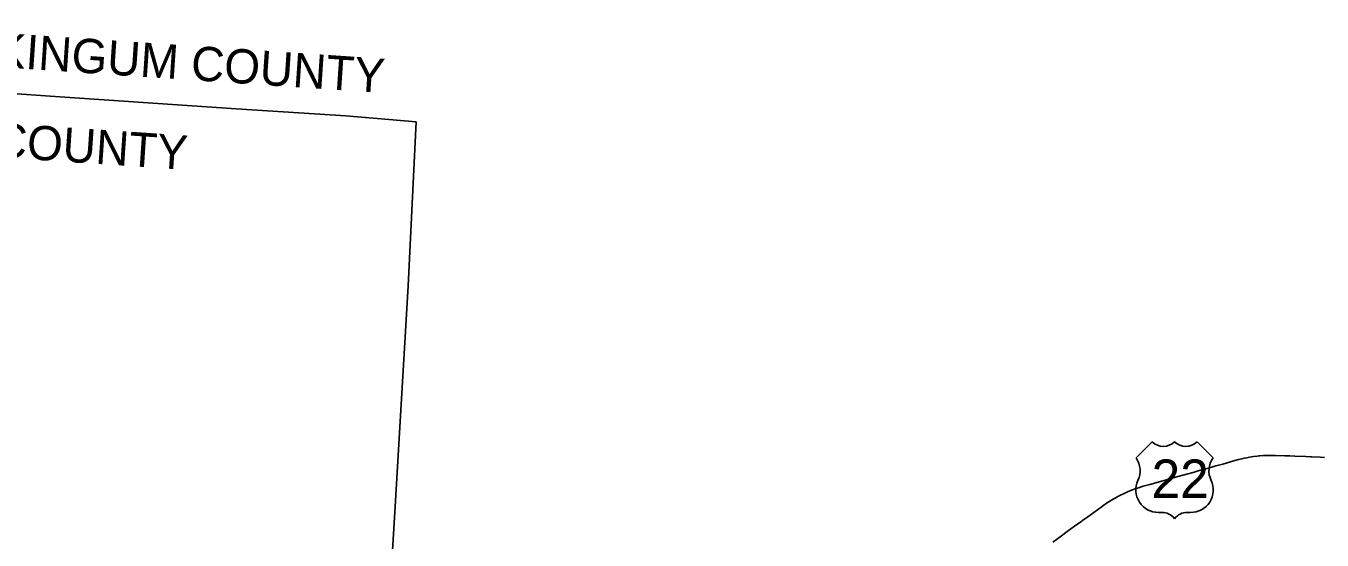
# Model space of a CAD drawing. Extents: x 2015843 to 2287843, y 623733 to 799733.
# Drawn here: x 2066735 to 2104493, y 678304 to 693294 of the extents above; entities that cross this region are included whole.
import ezdxf

# ---------------------------------------------------------------- set-up
doc = ezdxf.new("R2010")
doc.units = 0
for name, color, linetype in [('GM_X_County', 7, 'Continuous'), ('GM_X_County_Text', 7, 'Continuous'), ('GM_X_US_Location', 7, 'Continuous'), ('GM_X_US_Route', 7, 'Continuous'), ('GM_X_US_Shield', 7, 'Continuous')]:
    doc.layers.add(name, color=color, linetype=linetype)

msp = doc.modelspace()

# ---------------------------------------------------------------- linework, layer by layer
at = {"layer": 'GM_X_County'}
msp.add_lwpolyline([(2077417, 678005), (2077491, 679285), (2077631, 681596), (2077872, 685712), (2078099, 690497), (2076052, 690672), (2072864, 690877), (2067444, 691243), (2066344, 691320)], dxfattribs=at)
at = {"layer": 'GM_X_US_Route'}
msp.add_lwpolyline([(2096646, 678245), (2096860, 678398), (2097111, 678582), (2097350, 678754), (2097483, 678850), (2097498, 678861), (2097603, 678937), (2097735, 679034), (2098055, 679264), (2098217, 679376), (2098264, 679407), (2098313, 679439), (2098412, 679498), (2098486, 679540), (2098526, 679563), (2098599, 679601), (2098732, 679665), (2098821, 679706), (2098943, 679757), (2099050, 679798), (2099143, 679830), (2099284, 679874), (2099474, 679927), (2099853, 680032), (2100122, 680107), (2100296, 680155), (2100517, 680218), (2100738, 680279), (2100943, 680338), (2101180, 680403), (2101401, 680465), (2101607, 680522), (2101952, 680620), (2102062, 680652), (2102160, 680676), (2102232, 680692), (2102301, 680705), (2102383, 680721), (2102494, 680738), (2102599, 680751), (2102652, 680756), (2102679, 680759), (2102777, 680768), (2102861, 680772), (2103135, 680774), (2103407, 680765), (2103558, 680758), (2103696, 680750), (2104024, 680737), (2104159, 680731), (2104188, 680730), (2104433, 680720), (2104564, 680716)], dxfattribs=at)
at = {"layer": 'GM_X_US_Shield'}
for p, q in [((2099542, 681167), (2099075, 680700)), ((2101317, 680700), (2100850, 681167)), ((2099729, 679112), (2099823, 679112)), ((2100570, 679112), (2100663, 679112))]:
    msp.add_line(p, q, dxfattribs=at)
for centre, radius, start, end in [((2099869, 681501), 467, 225.573, 314.427), ((2100523, 681501), 467, 225.573, 314.427), ((2098540, 680325), 654, 334.5471, 35.0009), ((2101852, 680325), 654, 144.9991, 205.4529), ((2099722, 679766), 654, 154.8319, 270.6383), ((2100670, 679766), 654, 269.3617, 25.1681), ((2099823, 678646), 467, 36.8699, 90), ((2100570, 678646), 467, 90, 143.1301)]:
    msp.add_arc(centre, radius, start, end, dxfattribs=at)

# ---------------------------------------------------------------- texts
at = {"layer": 'GM_X_County_Text'}
for s, p in [('MUSKINGUM COUNTY', (2062849, 692303)), ('PERRY COUNTY', (2060810, 689813))]:
    msp.add_text(s, height=1000, rotation=356.1283, dxfattribs=at).set_placement(p)
at = {"layer": 'GM_X_US_Location'}
msp.add_text('22', height=1, rotation=0, dxfattribs=at).set_placement((2100175, 680179))
for s in ['0', '/']:
    msp.add_text(s, height=1, dxfattribs=at).set_placement((2100381, 680386))
at = {"layer": 'GM_X_US_Shield'}
msp.add_text('22', height=1120.7, dxfattribs=at).set_placement((2099526, 679533))

doc.saveas('drawing.dxf')
